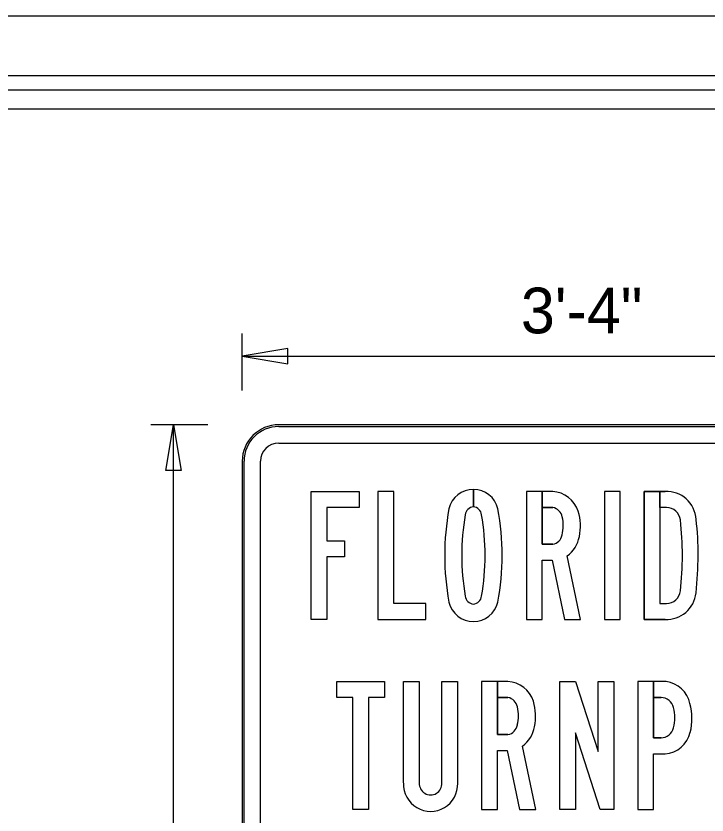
# Model space of a CAD drawing. Extents: x 17890628 to 17890844, y 17897693 to 17898031.
# Drawn here: x 17890808.4 to 17890818.49, y 17897988.15 to 17897999.81 of the extents above; entities that cross this region are included whole.
import ezdxf

# ---------------------------------------------------------------- set-up
doc = ezdxf.new("R2010")
doc.units = 0
for name, color, linetype in [('GSColorFill', 7, 'Continuous'), ('GSDims', 7, 'Continuous'), ('PlotBorder_dp', 7, 'Continuous'), ('SheetBorder_dp', 7, 'Continuous'), ('SheetLinesMisc2_dp', 7, 'Continuous')]:
    doc.layers.add(name, color=color, linetype=linetype)

msp = doc.modelspace()

# ---------------------------------------------------------------- linework, layer by layer
at = {"layer": 'GSColorFill'}
for p, q in [((17890821.835, 17897993.845), (17890812.234, 17897993.845)), ((17890821.835, 17897993.845), (17890812.234, 17897993.845)), ((17890821.835, 17897993.845), (17890812.234, 17897993.845)), ((17890812.234, 17897993.819), (17890821.835, 17897993.819)), ((17890812.234, 17897993.579), (17890821.835, 17897993.579)), ((17890811.701, 17897993.312), (17890811.701, 17897981.578)), ((17890811.701, 17897993.312), (17890811.701, 17897981.578)), ((17890811.701, 17897993.312), (17890811.701, 17897981.578)), ((17890811.728, 17897981.578), (17890811.728, 17897993.312)), ((17890811.968, 17897981.578), (17890811.968, 17897993.312)), ((17890815.077, 17897992.899), (17890815.077, 17897992.649)), ((17890815.077, 17897992.649), (17890815.077, 17897992.899)), ((17890815.077, 17897992.899), (17890815.077, 17897992.649)), ((17890815.077, 17897992.649), (17890815.077, 17897992.899)), ((17890817.897, 17897992.638), (17890817.798, 17897992.638)), ((17890817.815, 17897989.278), (17890817.706, 17897989.278)), ((17890817.815, 17897989.278), (17890817.706, 17897989.278)), ((17890817.815, 17897989.278), (17890817.815, 17897989.278)), ((17890817.706, 17897989.045), (17890817.876, 17897989.045)), ((17890814.617, 17897988.619), (17890814.617, 17897988.619)), ((17890814.617, 17897988.619), (17890814.617, 17897988.619)), ((17890814.617, 17897988.619), (17890814.617, 17897988.619))]:
    msp.add_line(p, q, dxfattribs=at)
for points in [[(17890813.193, 17897992.152), (17890813.193, 17897991.919), (17890812.938, 17897991.919), (17890812.938, 17897991.006), (17890812.708, 17897991.006), (17890812.708, 17897992.871), (17890813.407, 17897992.871), (17890813.407, 17897992.638), (17890812.938, 17897992.638), (17890812.938, 17897992.152)], [(17890813.193, 17897992.152), (17890813.193, 17897991.919), (17890812.938, 17897991.919), (17890812.938, 17897991.006), (17890812.708, 17897991.006), (17890812.708, 17897992.871), (17890813.407, 17897992.871), (17890813.407, 17897992.638), (17890812.938, 17897992.638), (17890812.938, 17897992.152)], [(17890813.193, 17897992.152), (17890813.193, 17897991.919), (17890812.938, 17897991.919), (17890812.938, 17897991.006), (17890812.708, 17897991.006), (17890812.708, 17897992.871), (17890813.407, 17897992.871), (17890813.407, 17897992.638), (17890812.938, 17897992.638), (17890812.938, 17897992.152)], [(17890813.912, 17897991.239), (17890813.912, 17897992.871), (17890813.682, 17897992.871), (17890813.682, 17897991.006), (17890814.38, 17897991.006), (17890814.38, 17897991.239)], [(17890813.912, 17897991.239), (17890813.912, 17897992.871), (17890813.682, 17897992.871), (17890813.682, 17897991.006), (17890814.38, 17897991.006), (17890814.38, 17897991.239)], [(17890813.912, 17897991.239), (17890813.912, 17897992.871), (17890813.682, 17897992.871), (17890813.682, 17897991.006), (17890814.38, 17897991.006), (17890814.38, 17897991.239)], [(17890817.219, 17897992.871), (17890816.989, 17897992.871), (17890816.989, 17897991.006), (17890817.219, 17897991.006)], [(17890817.219, 17897992.871), (17890816.989, 17897992.871), (17890816.989, 17897991.006), (17890817.219, 17897991.006)], [(17890817.219, 17897992.871), (17890816.989, 17897992.871), (17890816.989, 17897991.006), (17890817.219, 17897991.006)], [(17890813.78, 17897989.866), (17890813.546, 17897989.866), (17890813.546, 17897988.233), (17890813.316, 17897988.233), (17890813.316, 17897989.866), (17890813.081, 17897989.866), (17890813.081, 17897990.099), (17890813.78, 17897990.099)], [(17890813.78, 17897989.866), (17890813.546, 17897989.866), (17890813.546, 17897988.233), (17890813.316, 17897988.233), (17890813.316, 17897989.866), (17890813.081, 17897989.866), (17890813.081, 17897990.099), (17890813.78, 17897990.099)], [(17890813.78, 17897989.866), (17890813.546, 17897989.866), (17890813.546, 17897988.233), (17890813.316, 17897988.233), (17890813.316, 17897989.866), (17890813.081, 17897989.866), (17890813.081, 17897990.099), (17890813.78, 17897990.099)], [(17890816.566, 17897989.353), (17890816.566, 17897988.233), (17890816.336, 17897988.233), (17890816.336, 17897990.099), (17890816.566, 17897990.099), (17890816.897, 17897989.078), (17890816.897, 17897990.099), (17890817.126, 17897990.099), (17890817.126, 17897988.233), (17890816.929, 17897988.233)], [(17890816.566, 17897989.353), (17890816.566, 17897988.233), (17890816.336, 17897988.233), (17890816.336, 17897990.099), (17890816.566, 17897990.099), (17890816.897, 17897989.078), (17890816.897, 17897990.099), (17890817.126, 17897990.099), (17890817.126, 17897988.233), (17890816.929, 17897988.233)], [(17890816.566, 17897989.353), (17890816.566, 17897988.233), (17890816.336, 17897988.233), (17890816.336, 17897990.099), (17890816.566, 17897990.099), (17890816.897, 17897989.078), (17890816.897, 17897990.099), (17890817.126, 17897990.099), (17890817.126, 17897988.233), (17890816.929, 17897988.233)]]:
    msp.add_lwpolyline(points, close=True, dxfattribs=at)
for points in [[(17890816.234, 17897992.871), (17890815.85, 17897992.871), (17890815.85, 17897991.006), (17890816.08, 17897991.006), (17890816.08, 17897991.868), (17890816.224, 17897991.868), (17890816.405, 17897991.006)], [(17890816.08, 17897992.871), (17890815.85, 17897992.871), (17890815.85, 17897991.006), (17890816.08, 17897991.006), (17890816.08, 17897991.868), (17890816.224, 17897991.868), (17890816.405, 17897991.006), (17890816.64, 17897991.006), (17890816.446, 17897991.931)], [(17890816.08, 17897992.871), (17890815.85, 17897992.871), (17890815.85, 17897991.006), (17890816.08, 17897991.006), (17890816.08, 17897991.868), (17890816.224, 17897991.868), (17890816.405, 17897991.006), (17890816.64, 17897991.006), (17890816.446, 17897991.931)], [(17890816.234, 17897992.871), (17890816.08, 17897992.871), (17890816.08, 17897992.638), (17890816.234, 17897992.638)], [(17890816.234, 17897992.101), (17890816.08, 17897992.101), (17890816.08, 17897992.871)], [(17890816.234, 17897992.871), (17890816.08, 17897992.871), (17890816.08, 17897992.638), (17890816.234, 17897992.638)], [(17890816.234, 17897992.101), (17890816.08, 17897992.101), (17890816.08, 17897992.871)], [(17890817.875, 17897992.871), (17890817.568, 17897992.871), (17890817.568, 17897991.006), (17890817.875, 17897991.006)], [(17890817.875, 17897991.006), (17890817.568, 17897991.006), (17890817.568, 17897992.871), (17890817.798, 17897992.871), (17890817.798, 17897991.239), (17890817.897, 17897991.239)], [(17890817.875, 17897991.006), (17890817.568, 17897991.006), (17890817.568, 17897992.871), (17890817.798, 17897992.871), (17890817.798, 17897991.239), (17890817.897, 17897991.239)], [(17890817.897, 17897992.638), (17890817.798, 17897992.638), (17890817.798, 17897992.871), (17890817.875, 17897992.871)], [(17890817.897, 17897992.638), (17890817.798, 17897992.638), (17890817.798, 17897992.871), (17890817.875, 17897992.871)], [(17890816.234, 17897992.638), (17890816.08, 17897992.638), (17890816.08, 17897992.101), (17890816.234, 17897992.101)], [(17890817.798, 17897992.638), (17890817.798, 17897991.239), (17890817.897, 17897991.239)], [(17890816.405, 17897991.006), (17890816.64, 17897991.006), (17890816.446, 17897991.931)], [(17890814.056, 17897988.619), (17890814.056, 17897990.099), (17890814.286, 17897990.099), (17890814.286, 17897988.619)], [(17890814.056, 17897988.619), (17890814.056, 17897990.099), (17890814.286, 17897990.099), (17890814.286, 17897988.619)], [(17890814.056, 17897988.619), (17890814.056, 17897990.099), (17890814.286, 17897990.099), (17890814.286, 17897988.619)], [(17890814.617, 17897988.619), (17890814.617, 17897990.099), (17890814.846, 17897990.099), (17890814.846, 17897988.619)], [(17890814.617, 17897988.619), (17890814.617, 17897990.099), (17890814.846, 17897990.099), (17890814.846, 17897988.619)], [(17890814.617, 17897988.619), (17890814.617, 17897990.099), (17890814.846, 17897990.099), (17890814.846, 17897988.619)], [(17890815.58, 17897990.099), (17890815.196, 17897990.099), (17890815.196, 17897988.233), (17890815.426, 17897988.233), (17890815.426, 17897989.095), (17890815.57, 17897989.095), (17890815.751, 17897988.233)], [(17890815.426, 17897990.099), (17890815.196, 17897990.099), (17890815.196, 17897988.233), (17890815.426, 17897988.233), (17890815.426, 17897989.095), (17890815.57, 17897989.095), (17890815.751, 17897988.233), (17890815.986, 17897988.233), (17890815.792, 17897989.158)], [(17890815.426, 17897990.099), (17890815.196, 17897990.099), (17890815.196, 17897988.233), (17890815.426, 17897988.233), (17890815.426, 17897989.095), (17890815.57, 17897989.095), (17890815.751, 17897988.233), (17890815.986, 17897988.233), (17890815.792, 17897989.158)], [(17890815.58, 17897990.099), (17890815.426, 17897990.099), (17890815.426, 17897989.866), (17890815.58, 17897989.866)], [(17890815.58, 17897989.328), (17890815.426, 17897989.328), (17890815.426, 17897990.099)], [(17890815.58, 17897990.099), (17890815.426, 17897990.099), (17890815.426, 17897989.866), (17890815.58, 17897989.866)], [(17890815.58, 17897989.328), (17890815.426, 17897989.328), (17890815.426, 17897990.099)], [(17890817.89, 17897990.099), (17890817.476, 17897990.099), (17890817.476, 17897988.233), (17890817.706, 17897988.233), (17890817.706, 17897989.045)], [(17890817.706, 17897989.278), (17890817.706, 17897990.099), (17890817.476, 17897990.099), (17890817.476, 17897988.233), (17890817.706, 17897988.233), (17890817.706, 17897989.045), (17890817.876, 17897989.045)], [(17890817.706, 17897989.278), (17890817.706, 17897990.099), (17890817.476, 17897990.099), (17890817.476, 17897988.233), (17890817.706, 17897988.233), (17890817.706, 17897989.045), (17890817.876, 17897989.045)], [(17890817.89, 17897990.099), (17890817.706, 17897990.099), (17890817.706, 17897989.866), (17890817.815, 17897989.866)], [(17890817.89, 17897990.099), (17890817.706, 17897990.099), (17890817.706, 17897989.866), (17890817.815, 17897989.866)], [(17890815.58, 17897989.866), (17890815.426, 17897989.866), (17890815.426, 17897989.328), (17890815.58, 17897989.328)], [(17890817.815, 17897989.866), (17890817.706, 17897989.866), (17890817.706, 17897989.278), (17890817.815, 17897989.278)], [(17890815.751, 17897988.233), (17890815.986, 17897988.233), (17890815.792, 17897989.158)]]:
    msp.add_lwpolyline(points, dxfattribs=at)
for radius in [0.533, 0.533, 0.533, 0.507, 0.267]:
    msp.add_arc((17890812.234, 17897993.312), radius, 90, 180, dxfattribs=at)
for centre, major_axis, start_param, end_param in [((17890815.072, 17897992.53), (0, 0.37), 6.270788, 7.609689), ((17890815.072, 17897992.53), (0, 0.37), 6.270788, 7.609689), ((17890815.072, 17897992.53), (0, 0.37), 6.270788, 7.609689), ((17890815.081, 17897992.53), (0, 0.37), 4.956682, 6.295583), ((17890815.081, 17897992.53), (0, 0.37), 4.956682, 6.295331), ((17890815.081, 17897992.53), (0, 0.37), 4.956682, 6.295331), ((17890816.213, 17897992.452), (0, 0.419), 5.030251, 6.233097), ((17890816.213, 17897992.452), (0, 0.419), 5.030251, 6.233097), ((17890816.213, 17897992.452), (0, 0.419), 5.030251, 6.233097), ((17890817.9, 17897992.437), (0, 0.435), 4.775445, 6.340881), ((17890817.9, 17897992.437), (0, 0.435), 4.775445, 6.340881), ((17890817.9, 17897992.437), (0, 0.435), 4.775445, 6.340881), ((17890818.194, 17897991.955), (0, 3.59), 1.3849, 1.575497), ((17890818.194, 17897991.955), (0, 3.59), 1.3849, 1.575497), ((17890818.194, 17897991.955), (0, 3.59), 1.3849, 1.575497), ((17890815.09, 17897992.513), (0, 0.136), 0.099923, 1.436755), ((17890815.09, 17897992.513), (0, 0.136), 0.099923, 1.436755), ((17890815.09, 17897992.513), (0, 0.136), 0.099923, 1.436755), ((17890815.063, 17897992.513), (0, 0.136), 4.846431, 6.183262), ((17890815.063, 17897992.513), (0, 0.136), 4.846431, 6.182575), ((17890815.063, 17897992.513), (0, 0.136), 4.846431, 6.182575), ((17890811.959, 17897991.955), (0, 3.59), 4.707688, 4.898285), ((17890811.959, 17897991.955), (0, 3.59), 4.707688, 4.898285), ((17890811.959, 17897991.955), (0, 3.59), 4.707688, 4.898285), ((17890816.206, 17897992.467), (0, 0.173), 4.908761, 6.117799), ((17890816.206, 17897992.467), (0, 0.173), 4.908761, 6.117799), ((17890816.206, 17897992.467), (0, 0.173), 4.908761, 6.117799), ((17890815.903, 17897992.364), (0, 0.747), 4.509585, 5.011141), ((17890815.903, 17897992.364), (0, 0.747), 4.509585, 5.011141), ((17890815.903, 17897992.364), (0, 0.747), 4.509585, 5.011141), ((17890817.897, 17897992.433), (0, 0.205), 4.827653, 6.283185), ((17890817.897, 17897992.433), (0, 0.205), 4.827653, 6.283185), ((17890817.897, 17897992.433), (0, 0.205), 4.827653, 6.283185), ((17890818.554, 17897991.908), (0, 3.705), 1.401553, 1.562444), ((17890818.554, 17897991.908), (0, 3.705), 1.401553, 1.562444), ((17890818.554, 17897991.908), (0, 3.705), 1.401553, 1.562444), ((17890811.599, 17897991.908), (0, 3.705), 4.720742, 4.881632), ((17890811.599, 17897991.908), (0, 3.705), 4.720742, 4.881632), ((17890811.599, 17897991.908), (0, 3.705), 4.720742, 4.881632), ((17890815.84, 17897992.374), (0, 0.556), 4.465322, 4.943449), ((17890815.84, 17897992.374), (0, 0.556), 4.465322, 4.943449), ((17890815.84, 17897992.374), (0, 0.556), 4.465322, 4.943449), ((17890813.446, 17897991.91), (0, 4.754), 4.718466, 4.827653), ((17890813.446, 17897991.91), (0, 4.754), 4.718466, 4.827653), ((17890813.446, 17897991.91), (0, 4.754), 4.718466, 4.827653), ((17890813.446, 17897991.91), (0, 4.988), 4.718182, 4.823748), ((17890813.446, 17897991.91), (0, 4.988), 4.718182, 4.823748), ((17890813.446, 17897991.91), (0, 4.988), 4.718182, 4.823748), ((17890816.212, 17897992.263), (0, 0.163), 3.278526, 4.557126), ((17890816.212, 17897992.263), (0, 0.163), 3.278526, 4.557126), ((17890816.212, 17897992.263), (0, 0.163), 3.278526, 4.557126), ((17890816.181, 17897992.301), (0, 0.457), 3.768896, 4.519364), ((17890816.181, 17897992.301), (0, 0.457), 3.768896, 4.519364), ((17890816.181, 17897992.301), (0, 0.457), 3.768896, 4.519364), ((17890818.194, 17897991.922), (0, 3.59), 1.566095, 1.756692), ((17890818.194, 17897991.922), (0, 3.59), 1.566095, 1.756692), ((17890818.194, 17897991.922), (0, 3.59), 1.566095, 1.756692), ((17890818.554, 17897991.969), (0, 3.705), 1.579149, 1.740039), ((17890818.554, 17897991.969), (0, 3.705), 1.579149, 1.740039), ((17890818.554, 17897991.969), (0, 3.705), 1.579149, 1.740039), ((17890811.599, 17897991.969), (0, 3.705), 4.543146, 4.704036), ((17890811.599, 17897991.969), (0, 3.705), 4.543146, 4.704036), ((17890811.599, 17897991.969), (0, 3.705), 4.543146, 4.704036), ((17890811.959, 17897991.922), (0, 3.59), 4.526493, 4.71709), ((17890811.959, 17897991.922), (0, 3.59), 4.526493, 4.71709), ((17890811.959, 17897991.922), (0, 3.59), 4.526493, 4.71709), ((17890813.446, 17897991.967), (0, 4.754), 4.597125, 4.706312), ((17890813.446, 17897991.967), (0, 4.754), 4.597125, 4.706312), ((17890813.446, 17897991.967), (0, 4.754), 4.597125, 4.706312), ((17890812.972, 17897991.983), (0, 5.468), 4.604336, 4.704188), ((17890812.972, 17897991.983), (0, 5.468), 4.604336, 4.704188), ((17890812.972, 17897991.983), (0, 5.468), 4.604336, 4.704188), ((17890817.899, 17897991.442), (0, 0.437), 3.085351, 4.601199), ((17890817.899, 17897991.442), (0, 0.437), 3.085351, 4.601199), ((17890817.899, 17897991.442), (0, 0.437), 3.085351, 4.601199), ((17890817.897, 17897991.444), (0, 0.205), 3.141593, 4.597125), ((17890817.897, 17897991.444), (0, 0.205), 3.141593, 4.597125), ((17890817.897, 17897991.444), (0, 0.205), 3.141593, 4.597125), ((17890815.09, 17897991.364), (0, 0.136), 1.704838, 3.04167), ((17890815.09, 17897991.364), (0, 0.136), 1.704838, 3.04167), ((17890815.09, 17897991.364), (0, 0.136), 1.704838, 3.04167), ((17890815.063, 17897991.364), (0, 0.136), 3.241516, 4.578347), ((17890815.063, 17897991.364), (0, 0.136), 3.241516, 4.578347), ((17890815.063, 17897991.364), (0, 0.136), 3.241516, 4.578347), ((17890815.072, 17897991.347), (0, 0.37), 1.815089, 3.15399), ((17890815.072, 17897991.347), (0, 0.37), 1.815089, 3.15399), ((17890815.072, 17897991.347), (0, 0.37), 1.815089, 3.15399), ((17890815.081, 17897991.347), (0, 0.37), 3.129195, 4.468096), ((17890815.081, 17897991.347), (0, 0.37), 3.129195, 4.468096), ((17890815.081, 17897991.347), (0, 0.37), 3.129195, 4.468096), ((17890815.559, 17897989.68), (0, 0.42), 5.030251, 6.233097), ((17890815.559, 17897989.68), (0, 0.42), 5.030251, 6.233097), ((17890815.559, 17897989.68), (0, 0.42), 5.030251, 6.233097), ((17890817.838, 17897989.686), (0, 0.416), 4.933111, 6.154626), ((17890817.838, 17897989.686), (0, 0.416), 4.933111, 6.154626), ((17890817.838, 17897989.686), (0, 0.416), 4.933111, 6.154626), ((17890815.552, 17897989.695), (0, 0.173), 4.908761, 6.117799), ((17890815.552, 17897989.695), (0, 0.173), 4.908761, 6.117799), ((17890815.552, 17897989.695), (0, 0.173), 4.908761, 6.117799), ((17890815.248, 17897989.591), (0, 0.747), 4.509585, 5.011141), ((17890815.248, 17897989.591), (0, 0.747), 4.509585, 5.011141), ((17890815.248, 17897989.591), (0, 0.747), 4.509585, 5.011141), ((17890817.818, 17897989.678), (0, 0.187), 4.930878, 6.297268), ((17890817.818, 17897989.678), (0, 0.187), 4.930878, 6.297268), ((17890817.818, 17897989.678), (0, 0.187), 4.930878, 6.297268), ((17890817.432, 17897989.557), (0, 0.847), 4.47489, 4.974954), ((17890817.432, 17897989.557), (0, 0.847), 4.47489, 4.974954), ((17890817.432, 17897989.557), (0, 0.847), 4.47489, 4.974954), ((17890815.185, 17897989.601), (0, 0.557), 4.465322, 4.943449), ((17890815.185, 17897989.601), (0, 0.557), 4.465322, 4.943449), ((17890815.185, 17897989.601), (0, 0.557), 4.465322, 4.943449), ((17890817.498, 17897989.58), (0, 0.527), 4.698292, 4.980604), ((17890817.498, 17897989.58), (0, 0.527), 4.698292, 4.980604), ((17890817.498, 17897989.58), (0, 0.527), 4.698292, 4.980604), ((17890817.498, 17897989.565), (0, 0.527), 4.444174, 4.726486), ((17890817.498, 17897989.565), (0, 0.527), 4.444174, 4.726486), ((17890817.498, 17897989.565), (0, 0.527), 4.444174, 4.726486), ((17890815.558, 17897989.49), (0, 0.164), 3.278526, 4.557126), ((17890815.558, 17897989.49), (0, 0.164), 3.278526, 4.557126), ((17890815.558, 17897989.49), (0, 0.164), 3.278526, 4.557126), ((17890815.527, 17897989.528), (0, 0.458), 3.768896, 4.519364), ((17890815.527, 17897989.528), (0, 0.458), 3.768896, 4.519364), ((17890815.527, 17897989.528), (0, 0.458), 3.768896, 4.519364), ((17890817.818, 17897989.466), (0, 0.187), 3.12751, 4.4939), ((17890817.818, 17897989.466), (0, 0.187), 3.12751, 4.4939), ((17890817.818, 17897989.466), (0, 0.187), 3.12751, 4.4939), ((17890817.848, 17897989.457), (0, 0.413), 3.209861, 4.470855), ((17890817.848, 17897989.457), (0, 0.413), 3.209861, 4.470855), ((17890817.848, 17897989.457), (0, 0.413), 3.209861, 4.470855), ((17890814.451, 17897988.606), (0, 0.402), 1.539768, 4.743417), ((17890814.451, 17897988.606), (0, 0.402), 1.539768, 4.743417), ((17890814.451, 17897988.606), (0, 0.402), 1.539768, 4.743417), ((17890814.451, 17897988.613), (0, 0.168), 1.536895, 4.746291), ((17890814.451, 17897988.613), (0, 0.168), 1.536895, 4.746291), ((17890814.451, 17897988.613), (0, 0.168), 1.536895, 4.746291)]:
    msp.add_ellipse(centre, major_axis=major_axis, ratio=0.985, start_param=start_param, end_param=end_param, dxfattribs=at)
at = {"layer": 'GSDims'}
for p, q in [((17890811.698, 17897994.346), (17890811.698, 17897995.179)), ((17890811.698, 17897994.846), (17890822.365, 17897994.846)), ((17890811.198, 17897993.846), (17890810.365, 17897993.846)), ((17890810.698, 17897981.045), (17890810.698, 17897993.846))]:
    msp.add_line(p, q, dxfattribs=at)
for points in [[(17890811.698, 17897994.846), (17890812.365, 17897994.735), (17890812.365, 17897994.957)], [(17890810.698, 17897993.846), (17890810.81, 17897993.179), (17890810.587, 17897993.179)]]:
    msp.add_lwpolyline(points, close=True, dxfattribs=at)
at = {"layer": 'PlotBorder_dp'}
msp.add_lwpolyline([(17890700.471, 17897907.61), (17890843.989, 17897907.61), (17890843.989, 17897999.809), (17890700.471, 17897999.809)], close=True, dxfattribs=at)
at = {"layer": 'SheetBorder_dp'}
msp.add_line((17890705.254, 17897998.94), (17890839.205, 17897998.94), dxfattribs=at)
at = {"layer": 'SheetLinesMisc2_dp'}
for p, q in [((17890705.5, 17897998.732), (17890839.233, 17897998.732)), ((17890793.11, 17897998.455), (17890838.594, 17897998.455))]:
    msp.add_line(p, q, dxfattribs=at)

# ---------------------------------------------------------------- texts
at = {"layer": 'GSDims'}
msp.add_text('3\'-4"', height=0.6667, dxfattribs=at).set_placement((17890815.769, 17897995.179))

doc.saveas('drawing.dxf')
